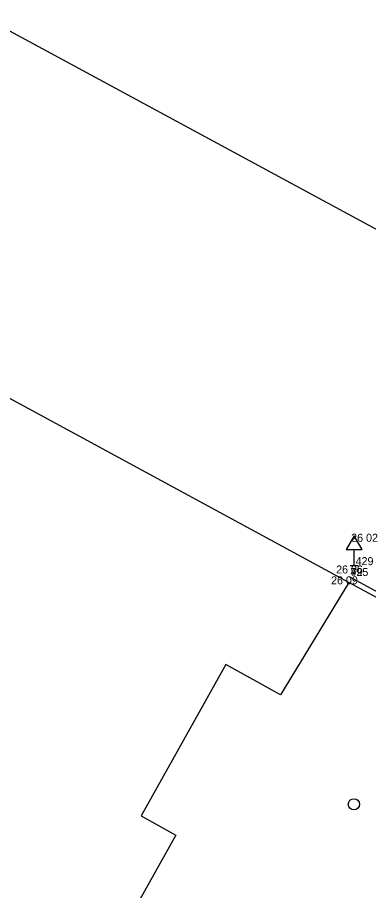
# Model space of a CAD drawing. Extents: x -702257 to -701487, y -1009871 to -1008841.
# Drawn here: x -701793.04 to -701782.08, y -1009385.88 to -1009358.61 of the extents above; entities that cross this region are included whole.
import ezdxf

# ---------------------------------------------------------------- set-up
doc = ezdxf.new("R2010")
doc.units = 0
for name, color, linetype in [('Z_body', 7, 'Continuous'), ('Z_body_cisla', 7, 'Continuous'), ('Z_body_vysky_redukovane', 7, 'Continuous'), ('Z_budova', 7, 'Continuous'), ('Z_dopravni_znacky', 7, 'Continuous'), ('Z_katastr_hranice', 7, 'Continuous'), ('Z_katastr_vnitrni_kresba', 7, 'Continuous'), ('Z_katastr_znacky_budov', 7, 'Continuous')]:
    doc.layers.add(name, color=color, linetype=linetype)

# ---------------------------------------------------------------- blocks, each defined once
blk = doc.blocks.new('Z527_1')
for p, q in [((0, 0.925), (-0.25, 0.5)), ((0.25, 0.5), (0, 0.925)), ((-0.25, 0.5), (0.25, 0.5)), ((0, 0), (0, 0.5)), ((-0.125, 0), (0.125, 0))]:
    blk.add_line(p, q)
blk = doc.blocks.new('Z527_2')
for p, q in [((0, 0.925), (-0.25, 0.5)), ((0.25, 0.5), (0, 0.925)), ((-0.25, 0.5), (0.25, 0.5)), ((0, 0), (0, 0.5)), ((-0.125, 0), (0.125, 0))]:
    blk.add_line(p, q)
blk = doc.blocks.new('POINT_DISPLAY')
blk.add_line((0, 0), (0, 0))

msp = doc.modelspace()

# ---------------------------------------------------------------- linework, layer by layer
at = {"layer": 'Z_budova'}
msp.add_line((-701782.69, -1009376.07), (-701773.71, -1009381.04), dxfattribs=at)
at = {"layer": 'Z_katastr_hranice'}
for p, q in [((-701773.66, -1009369.67), (-701794.93, -1009358.15)), ((-701782.7, -1009376.26), (-701795.9, -1009369.1)), ((-701773.73, -1009381.12), (-701782.7, -1009376.26))]:
    msp.add_line(p, q, dxfattribs=at)
at = {"layer": 'Z_katastr_vnitrni_kresba'}
for p, q in [((-701782.7, -1009376.26), (-701784.83, -1009379.77)), ((-701786.54, -1009378.82), (-701789.18, -1009383.55)), ((-701784.83, -1009379.77), (-701786.54, -1009378.82)), ((-701789.18, -1009383.55), (-701788.1, -1009384.15)), ((-701788.1, -1009384.15), (-701790.09, -1009387.7))]:
    msp.add_line(p, q, dxfattribs=at)
at = {"layer": 'Z_katastr_znacky_budov'}
msp.add_circle((-701782.537, -1009383.189), 0.175, dxfattribs=at)

# ---------------------------------------------------------------- block references
at = {"layer": 'Z_body'}
for p in [(-701782.53, -1009375.73), (-701782.69, -1009376.07)]:
    msp.add_blockref('POINT_DISPLAY', p, dxfattribs=at)
at = {"layer": 'Z_dopravni_znacky'}
for name in ['Z527_1', 'Z527_2']:
    msp.add_blockref(name, (-701782.53, -1009375.73), dxfattribs=at)

# ---------------------------------------------------------------- texts
at = {"layer": 'Z_body_cisla'}
for s, p in [('429', (-701782.485, -1009375.72)), ('42', (-701782.645, -1009376.06)), ('795', (-701782.645, -1009376.06))]:
    msp.add_text(s, height=0.25, dxfattribs=at).set_placement(p)
at = {"layer": 'Z_body_vysky_redukovane'}
for s, p in [('26 02', (-701782.623, -1009374.99)), ('26 06', (-701783.093, -1009375.98)), ('26 09', (-701783.252, -1009376.32)), ('26 09', (-701783.252, -1009376.32))]:
    msp.add_text(s, height=0.25, dxfattribs=at).set_placement(p)

doc.saveas('drawing.dxf')
